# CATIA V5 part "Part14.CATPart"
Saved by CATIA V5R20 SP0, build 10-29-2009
Part number: 9FP041218-20130117
Revision: ANY
Definition: UNKNOWN
Nomenclature: 9FP041218-20130117
Source: Unknown
Bounding box of the stored display mesh (mm): x -9 to 9, y -9 to 9, z 0 to 8
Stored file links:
  C:\Users\Utente\Desktop\IO LAVORO\3D X SITO CF\CUMSA\3D files PF\PF 1242WB\Part14.CATPart
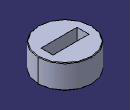
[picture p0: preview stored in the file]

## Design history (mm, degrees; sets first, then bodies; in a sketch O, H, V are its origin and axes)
Body1 "Chaflán1" (main body)
  Solid1: solid without history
